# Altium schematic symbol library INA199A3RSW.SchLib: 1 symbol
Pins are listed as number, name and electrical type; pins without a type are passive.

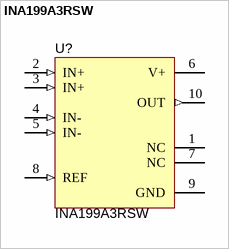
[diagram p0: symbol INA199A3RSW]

## INA199A3RSW
designator U?
Voltage Output, High or Low Side Measurement, Bi-Directional Zerø-Drift Series Current-Shunt Monitor,  RSW0010A; Manufacturer: Texas Instruments; CompType: IC; U/M: EA
footprint RSW0010A
pins: 1 NC, 2 IN+ (in), 3 IN+ (in), 4 IN- (in), 5 IN- (in), 6 V+ (power), 7 NC, 8 REF (in), 9 GND (power), 10 OUT (out)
